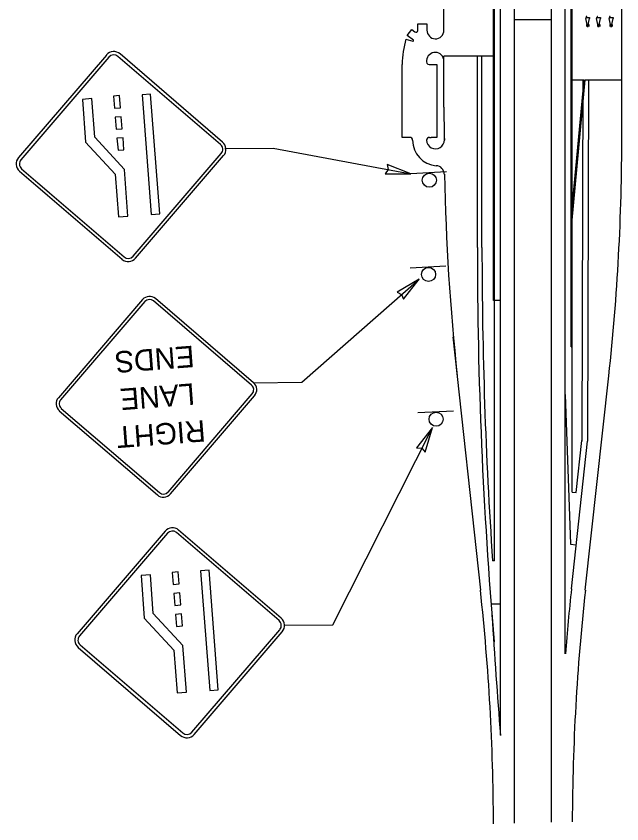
# Model space of a CAD drawing. Extents: x -102643 to -98250, y 54554 to 62384.
# Drawn here: x -101443 to -100397, y 55116 to 56510 of the extents above; entities that cross this region are included whole.
import ezdxf

# ---------------------------------------------------------------- set-up
doc = ezdxf.new("R2010")
doc.units = 0
for name, color, linetype in [('LeaderLine_dp', 7, 'Continuous'), ('RoadwayMisc', 7, 'Continuous'), ('SignPanel', 7, 'Continuous'), ('SignSupport', 7, 'Continuous')]:
    doc.layers.add(name, color=color, linetype=linetype)

msp = doc.modelspace()

# ---------------------------------------------------------------- linework, layer by layer
at = {"layer": 'LeaderLine_dp'}
for p, q in [((-101082.8, 56281.7), (-100999.4, 56282.5)), ((-100999.4, 56282.5), (-100761.4, 56238.2)), ((-100761.4, 56238.2), (-100802.6, 56254.4)), ((-100802.6, 56254.4), (-100800.9, 56245.5)), ((-100800.9, 56245.5), (-100805.6, 56238.2)), ((-100805.6, 56238.2), (-100761.4, 56238.2)), ((-100949.7, 55878.4), (-100747.2, 56056.5)), ((-100747.2, 56056.5), (-100785.4, 56034.1)), ((-100774.5, 56021.7), (-100747.2, 56056.5)), ((-100785.4, 56034.1), (-100777.4, 56030)), ((-100777.4, 56030), (-100774.5, 56021.7)), ((-101033.1, 55877.6), (-100949.7, 55878.4)), ((-100896.3, 55460.1), (-100724.4, 55800.5)), ((-100724.4, 55800.5), (-100751.5, 55765.5)), ((-100736.8, 55758), (-100724.4, 55800.5)), ((-100751.5, 55765.5), (-100742.5, 55764.6)), ((-100742.5, 55764.6), (-100736.8, 55758)), ((-100979.6, 55459.3), (-100896.3, 55460.1))]:
    msp.add_line(p, q, dxfattribs=at)
at = {"layer": 'RoadwayMisc'}
for p, q in [((-100582.8, 55117.4), (-100582.8, 62374)), ((-100518.8, 55119.1), (-100518.8, 62374)), ((-100494.8, 55409.7), (-100494.8, 57849.7)), ((-100484.8, 55939.6), (-100484.8, 57219.6)), ((-100482.8, 55689), (-100482.8, 57219.6)), ((-100618.8, 56019.6), (-100618.8, 57119.6)), ((-100616.8, 56019.6), (-100616.8, 57119.6)), ((-100606.8, 56019.6), (-100606.8, 57119.6)), ((-100704.4, 56486.1), (-100704.4, 56804.6)), ((-100397.1, 56304.6), (-100397.1, 56804.6)), ((-100582.8, 56504.6), (-100518.8, 56504.6)), ((-100459.6, 56508), (-100452.8, 56508)), ((-100459.6, 56508), (-100459.6, 56506)), ((-100457.2, 56496), (-100459.6, 56506)), ((-100457.8, 56509.6), (-100458.8, 56509.6)), ((-100458.8, 56509.6), (-100458.8, 56508.6)), ((-100458.8, 56508.6), (-100457.8, 56508.6)), ((-100457.8, 56508.6), (-100457.8, 56509.6)), ((-100455.2, 56496), (-100452.8, 56506)), ((-100452.8, 56508), (-100452.8, 56506)), ((-100440.8, 56508), (-100434, 56508)), ((-100440.8, 56508), (-100440.8, 56506)), ((-100438.4, 56496), (-100440.8, 56506)), ((-100439, 56509.6), (-100440, 56509.6)), ((-100440, 56509.6), (-100440, 56508.6)), ((-100440, 56508.6), (-100439, 56508.6)), ((-100439, 56508.6), (-100439, 56509.6)), ((-100436.4, 56496), (-100434, 56506)), ((-100434, 56508), (-100434, 56506)), ((-100419, 56508), (-100412.2, 56508)), ((-100419, 56508), (-100419, 56506)), ((-100416.6, 56496), (-100419, 56506)), ((-100417.2, 56509.6), (-100418.2, 56509.6)), ((-100418.2, 56509.6), (-100418.2, 56508.6)), ((-100418.2, 56508.6), (-100417.2, 56508.6)), ((-100417.2, 56508.6), (-100417.2, 56509.6)), ((-100414.6, 56496), (-100412.2, 56506)), ((-100412.2, 56508), (-100412.2, 56506)), ((-100749.7, 56485.6), (-100749.7, 56496.9)), ((-100749.7, 56496.9), (-100749.7, 56496.9)), ((-100749.7, 56496.9), (-100733.7, 56496.9)), ((-100733.7, 56496.9), (-100733.7, 56496.9)), ((-100733.7, 56496.9), (-100733.7, 56486.1)), ((-100458.2, 56496), (-100458.2, 56492.5)), ((-100458.2, 56496), (-100457.2, 56496)), ((-100457.2, 56496), (-100457.2, 56492.5)), ((-100457.2, 56496), (-100455.2, 56496)), ((-100457.2, 56492.5), (-100455.2, 56492.5)), ((-100455.2, 56496), (-100455.2, 56492.5)), ((-100454.2, 56496), (-100455.2, 56496)), ((-100454.2, 56496), (-100454.2, 56492.5)), ((-100439.4, 56496), (-100438.4, 56496)), ((-100439.4, 56496), (-100439.4, 56492.5)), ((-100438.4, 56496), (-100438.4, 56492.5)), ((-100438.4, 56496), (-100436.4, 56496)), ((-100438.4, 56492.5), (-100436.4, 56492.5)), ((-100436.4, 56496), (-100436.4, 56492.5)), ((-100435.4, 56496), (-100436.4, 56496)), ((-100435.4, 56496), (-100435.4, 56492.5)), ((-100417.6, 56496), (-100417.6, 56492.5)), ((-100417.6, 56496), (-100416.6, 56496)), ((-100416.6, 56496), (-100416.6, 56492.5)), ((-100416.6, 56496), (-100414.6, 56496)), ((-100416.6, 56492.5), (-100414.6, 56492.5)), ((-100413.6, 56496), (-100414.6, 56496)), ((-100414.6, 56496), (-100414.6, 56492.5)), ((-100413.6, 56496), (-100413.6, 56492.5)), ((-100704.4, 56353.3), (-100704.4, 56441)), ((-100618.8, 56441), (-100704.4, 56441)), ((-100646.7, 56111.2), (-100646.7, 56441)), ((-100638.7, 56111.2), (-100638.7, 56441)), ((-100482.8, 56400.6), (-100462.3, 56400.6)), ((-100482.8, 56180), (-100462.3, 56400.6)), ((-100482.8, 56158.3), (-100460.3, 56400.6)), ((-100464.5, 56400.7), (-100466.2, 55777.1)), ((-100460.3, 56400.6), (-100397.1, 56400.6)), ((-100454.5, 56400.7), (-100456.2, 55777)), ((-100763.4, 56301.1), (-100768.9, 56301.1)), ((-100729.4, 56301.1), (-100726.3, 56301.1)), ((-100616.8, 56019.6), (-100618.8, 56019.6)), ((-100606.8, 56019.6), (-100618.8, 56019.6)), ((-100616.8, 55570.6), (-100616.8, 56019.6)), ((-100606.8, 55269.4), (-100606.8, 56019.6)), ((-100640.9, 55519.7), (-100688.7, 55956.7)), ((-100484.7, 55939.6), (-100482.7, 55939.6)), ((-100460.2, 55519.6), (-100419.7, 55889.6)), ((-100494.8, 55857.6), (-100485.7, 55599.1)), ((-100494.8, 55840.2), (-100494.1, 55839.4)), ((-100484, 55522.2), (-100456.2, 55777)), ((-100475.9, 55688.3), (-100466.1, 55778.1)), ((-100482.8, 55689), (-100475.9, 55688.3)), ((-100485.7, 55599.1), (-100475.8, 55598)), ((-100616.8, 55570.6), (-100620.4, 55570.6)), ((-100606.8, 55495.6), (-100623, 55495.6))]:
    msp.add_line(p, q, dxfattribs=at)
for points in [[(-100757.2, 56469), (-100767.9, 56477), (-100767.9, 56477), (-100760, 56487.4), (-100760, 56487.4), (-100754.5, 56483.2)], [(-100769.9, 56470.8), (-100758.1, 56467.2)], [(-100776.4, 56301.1), (-100776.4, 56301.1), (-100776.4, 56427.1)], [(-100729.7, 56427.1), (-100716.4, 56427.1), (-100716.4, 56301.1), (-100726.3, 56301.1)], [(-100768.9, 56301.1), (-100776.4, 56301.1)]]:
    msp.add_lwpolyline(points, dxfattribs=at)
for centre, radius, start, end in [((-100752.7, 56485.6), 3, 233.0709, 0.0008), ((-100718.7, 56486.1), 15, 180, 267.2045), ((-100719.4, 56486.1), 15, 269.9986, 359.9981), ((-100626.4, 56427.1), 150, 163.0703, 179.9985), ((-100757.8, 56468.2), 1, 253.0525, 53.063), ((-100719.4, 56432.7), 15, 359.9989, 176.5954), ((-100729.7, 56432.1), 5, 160.5302, 270), ((-98794.4, 56353.2), 1910, 179.9968, 181.7147), ((-100763.4, 56296.1), 5, 359.9881, 89.9954), ((-100714.4, 56296.1), 44, 179.995, 265.6625), ((-100729.4, 56296.1), 5, 89.9925, 179.9951), ((-100719, 56296.6), 15.4, 181.7192, 1.7209), ((-96884.7, 56304.6), 3819.2, 180, 180.1138), ((-104216.8, 56304.6), 3819.7, 353.7628, 360), ((-100718.8, 56237.3), 15, 1.0063, 85.6625), ((-96884.7, 56304.6), 3819.2, 181.0063, 186.2372), ((-92646.7, 56111.2), 8000, 179.99992, 184.87894), ((-92646.7, 56111.2), 7992, 179.99992, 183.87996), ((-104438.5, 55104.6), 3819.7, 0.1778, 6.2372), ((-96663.1, 55104.6), 3843.7, 173.7628, 175.4472), ((-96663.1, 55104.6), 3819.7, 173.7628, 179.7687), ((-86274.8, 56389.3), 14375.7, 183.63987, 184.46998)]:
    msp.add_arc(centre, radius, start, end, dxfattribs=at)
at = {"layer": 'SignPanel'}
for p, q in [((-101287.2, 56443.2), (-101439.1, 56266.2)), ((-101283, 56439.6), (-101434.9, 56262.6)), ((-101090.3, 56288.9), (-101267.3, 56440.8)), ((-101086.7, 56293.1), (-101263.7, 56445)), ((-101312.6, 56367.9), (-101328.7, 56366.7)), ((-101328.7, 56366.7), (-101323.1, 56293)), ((-101307.5, 56301.2), (-101312.6, 56367.9)), ((-101264.8, 56373.1), (-101275.1, 56372.2)), ((-101275.1, 56372.2), (-101273.4, 56351.4)), ((-101263, 56352.3), (-101264.8, 56373.1)), ((-101211, 56375.7), (-101225.7, 56374.6)), ((-101225.7, 56374.6), (-101210, 56168.2)), ((-101195.3, 56169.4), (-101211, 56375.7)), ((-101273.4, 56351.4), (-101263, 56352.3)), ((-101261.7, 56336.7), (-101272.1, 56335.9)), ((-101272.1, 56335.9), (-101270.3, 56315.1)), ((-101259.9, 56316), (-101261.7, 56336.7)), ((-101270.3, 56315.1), (-101259.9, 56316)), ((-101256.3, 56245.9), (-101307.5, 56301.2)), ((-101258.6, 56300.4), (-101269, 56299.5)), ((-101269, 56299.5), (-101267.2, 56278.8)), ((-101256.9, 56279.7), (-101258.6, 56300.4)), ((-101323.1, 56293), (-101271.9, 56237.7)), ((-101267.2, 56278.8), (-101256.9, 56279.7)), ((-101241, 56096.2), (-101089.1, 56273.2)), ((-101236.8, 56092.5), (-101084.9, 56269.6)), ((-101437.4, 56242.7), (-101260.3, 56090.8)), ((-101433.7, 56246.9), (-101256.7, 56095)), ((-101250.1, 56165.2), (-101256.3, 56245.9)), ((-101271.9, 56237.7), (-101266.2, 56163.9)), ((-101266.2, 56163.9), (-101250.1, 56165.2)), ((-101210, 56168.2), (-101195.3, 56169.4)), ((-101225, 56021.2), (-101370.3, 55851.8)), ((-101220.9, 56017.8), (-101366.3, 55848.4)), ((-101036.6, 55873.5), (-101206, 56018.9)), ((-101033.1, 55877.6), (-101202.5, 56022.9)), ((-101180.8, 55689.1), (-101035.4, 55858.5)), ((-101176.8, 55685.7), (-101031.4, 55855.1)), ((-101368.6, 55829.3), (-101199.2, 55684)), ((-101365.2, 55833.4), (-101195.8, 55688)), ((-101186, 55621.6), (-101338, 55444.5)), ((-101181.8, 55617.9), (-101333.7, 55440.9)), ((-100989.1, 55467.2), (-101166.1, 55619.1)), ((-100985.5, 55471.4), (-101162.5, 55623.4)), ((-101211.4, 55546.3), (-101227.5, 55545)), ((-101227.5, 55545), (-101221.9, 55471.3)), ((-101206.3, 55479.5), (-101211.4, 55546.3)), ((-101163.6, 55551.4), (-101174, 55550.5)), ((-101174, 55550.5), (-101172.2, 55529.7)), ((-101161.8, 55530.6), (-101163.6, 55551.4)), ((-101109.8, 55554), (-101124.6, 55552.9)), ((-101124.6, 55552.9), (-101108.8, 55346.6)), ((-101094.1, 55347.7), (-101109.8, 55554)), ((-101172.2, 55529.7), (-101161.8, 55530.6)), ((-101160.5, 55515), (-101170.9, 55514.2)), ((-101158.7, 55494.3), (-101160.5, 55515)), ((-101170.9, 55514.2), (-101169.1, 55493.4)), ((-101169.1, 55493.4), (-101158.7, 55494.3)), ((-101155.1, 55424.2), (-101206.3, 55479.5)), ((-101157.4, 55478.7), (-101167.8, 55477.8)), ((-101167.8, 55477.8), (-101166.1, 55457.1)), ((-101155.7, 55458), (-101157.4, 55478.7)), ((-101221.9, 55471.3), (-101170.7, 55416)), ((-101166.1, 55457.1), (-101155.7, 55458)), ((-101139.8, 55274.5), (-100987.9, 55451.5)), ((-101135.6, 55270.9), (-100983.7, 55447.9)), ((-101336.2, 55421), (-101159.1, 55269.1)), ((-101332.5, 55425.2), (-101155.5, 55273.3)), ((-101148.9, 55343.5), (-101155.1, 55424.2)), ((-101170.7, 55416), (-101165.1, 55342.3)), ((-101108.8, 55346.6), (-101094.1, 55347.7)), ((-101165.1, 55342.3), (-101148.9, 55343.5))]:
    msp.add_line(p, q, dxfattribs=at)
for centre, radius, start, end in [((-101274.6, 56432.4), 16.7, 49.3622, 139.3622), ((-101274.6, 56432.4), 11.1, 49.3622, 139.3622), ((-101097.5, 56280.4), 11.1, 319.3622, 49.3622), ((-101097.5, 56280.4), 16.7, 319.3622, 49.3622), ((-101426.5, 56255.3), 16.7, 139.3622, 229.3622), ((-101426.5, 56255.3), 11.1, 139.3622, 229.3622), ((-101249.5, 56103.4), 16.7, 229.3622, 319.3622), ((-101249.5, 56103.4), 11.1, 229.3622, 319.3622), ((-101212.9, 56010.8), 15.9, 49.3622, 139.3622), ((-101212.9, 56010.8), 10.6, 49.3622, 139.3622), ((-101043.5, 55865.5), 15.9, 319.3622, 49.3622), ((-101043.5, 55865.5), 10.6, 319.3622, 49.3622), ((-101358.2, 55841.4), 15.9, 139.3622, 229.3622), ((-101358.2, 55841.4), 10.6, 139.3622, 229.3622), ((-101188.9, 55696.1), 15.9, 229.3622, 319.3622), ((-101188.9, 55696.1), 10.6, 229.3622, 319.3622), ((-101173.4, 55610.7), 16.7, 49.3622, 139.3622), ((-101173.4, 55610.7), 11.1, 49.3622, 139.3622), ((-100996.3, 55458.8), 11.1, 319.3622, 49.3622), ((-100996.3, 55458.8), 16.7, 319.3622, 49.3622), ((-101325.3, 55433.7), 16.7, 139.3622, 229.3622), ((-101325.3, 55433.7), 11.1, 139.3622, 229.3622), ((-101148.3, 55281.7), 16.7, 229.3622, 319.3622), ((-101148.3, 55281.7), 11.1, 229.3622, 319.3622)]:
    msp.add_arc(centre, radius, start, end, dxfattribs=at)
at = {"layer": 'SignSupport'}
for p, q in [((-100699.8, 56241.4), (-100761.4, 56238.2)), ((-100701.2, 56078.8), (-100762.8, 56075.5)), ((-100688.1, 55828.9), (-100749.7, 55825.6))]:
    msp.add_line(p, q, dxfattribs=at)
for centre in [(-100729.6, 56227.2), (-100731, 56064.6), (-100717.9, 55814.7)]:
    msp.add_circle(centre, 12.2, dxfattribs=at)

# ---------------------------------------------------------------- texts
at = {"layer": 'SignPanel'}
for s, p in [('ENDS', (-101136.9, 55941.8)), ('LANE', (-101136.3, 55876.9)), ('RIGHT', (-101117.7, 55813.4))]:
    msp.add_text(s, height=36.99, rotation=184.3622, dxfattribs=at).set_placement(p)

doc.saveas('drawing.dxf')
